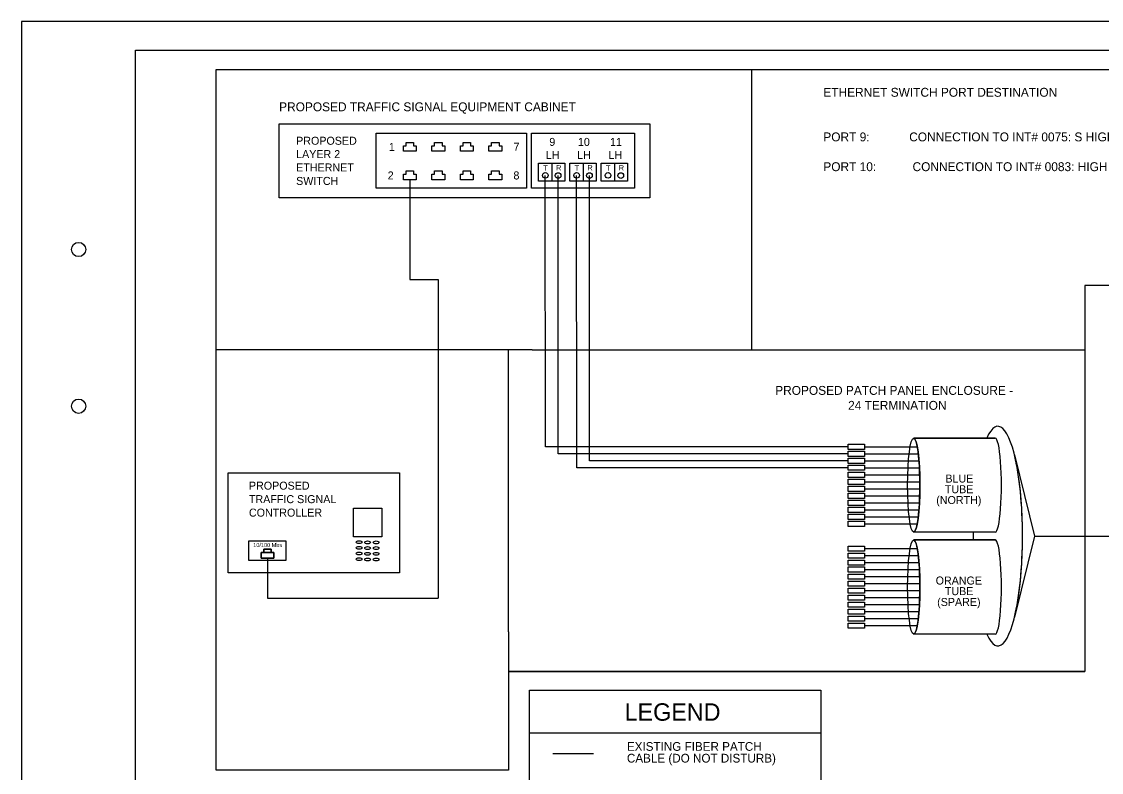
# Model space of a CAD drawing. Extents: x 1805893 to 1833564, y 708898 to 716199.
# Drawn here: x 1831322.5 to 1831701.4, y 713434.4 to 713697.9 of the extents above; entities that cross this region are included whole.
import ezdxf

# ---------------------------------------------------------------- set-up
doc = ezdxf.new("R2010")
doc.units = 0
for name, color, linetype in [('BR_P_Sub_Hidden', 7, 'Continuous'), ('SH_Border', 7, 'Continuous'), ('SH_Cut_Line', 7, 'Continuous'), ('SH_Data', 7, 'Continuous')]:
    doc.layers.add(name, color=color, linetype=linetype)

msp = doc.modelspace()

# ---------------------------------------------------------------- linework, layer by layer
at = {"layer": 'BR_P_Sub_Hidden'}
for p, q in [((1831578.6, 713681.08), (1831578.6, 713582.72)), ((1831501.65, 713582.72), (1831390.73, 713582.72)), ((1831493.37, 713483.67), (1831493.37, 713582.72)), ((1831501.65, 713582.72), (1831695.5, 713582.72)), ((1831493.37, 713483.67), (1831493.37, 713435.11)), ((1831493.37, 713469.79), (1831695.5, 713469.79))]:
    msp.add_line(p, q, dxfattribs=at)
msp.add_lwpolyline([(1831493.37, 713435.11), (1831390.73, 713435.11), (1831390.73, 713681.08), (1831814.91, 713681.08), (1831814.91, 713605.3), (1831695.5, 713605.3), (1831695.5, 713469.79), (1831493.37, 713469.79)], close=True, dxfattribs=at)
at = {"layer": 'SH_Border'}
msp.add_lwpolyline([(1831362.49, 713687.91), (1831992.49, 713687.91), (1831992.49, 713267.91), (1831362.49, 713267.91)], close=True, dxfattribs=at)
for centre in [(1831342.49, 713617.91), (1831342.49, 713562.91)]:
    msp.add_circle(centre, 2.5, dxfattribs=at)
at = {"layer": 'SH_Cut_Line'}
msp.add_lwpolyline([(1831322.49, 713257.91), (1832002.49, 713257.91), (1832002.49, 713697.91), (1831322.49, 713697.91)], close=True, dxfattribs=at)
at = {"layer": 'SH_Data'}
for p, q in [((1831508.49, 713648.17), (1831508.49, 713641.9)), ((1831519.49, 713648.17), (1831519.49, 713641.9)), ((1831530.49, 713648.17), (1831530.49, 713641.9)), ((1831506.28, 713548.67), (1831506.25, 713643.93)), ((1831510.79, 713546.21), (1831510.74, 713643.86)), ((1831517.28, 713541.3), (1831517.25, 713643.93)), ((1831521.79, 713543.75), (1831521.74, 713643.86)), ((1831458.71, 713642.38), (1831458.71, 713607.38)), ((1831458.71, 713607.38), (1831468.63, 713607.38)), ((1831468.63, 713607.38), (1831468.63, 713495.52)), ((1831612.48, 713548.67), (1831506.28, 713548.67)), ((1831618.22, 713548.67), (1831636.75, 713548.67)), ((1831664.14, 713551.7), (1831635.51, 713551.7)), ((1831635.51, 713551.7), (1831661.12, 713551.7)), ((1831635.51, 713551.7), (1831664.14, 713551.7)), ((1831612.48, 713546.21), (1831510.79, 713546.21)), ((1831618.22, 713546.21), (1831637.11, 713546.21)), ((1831670.87, 713545.81), (1831677.88, 713517.31)), ((1831612.48, 713541.3), (1831517.28, 713541.3)), ((1831612.48, 713543.75), (1831521.79, 713543.75)), ((1831618.22, 713543.75), (1831637.34, 713543.75)), ((1831618.22, 713541.3), (1831637.5, 713541.3)), ((1831618.22, 713538.84), (1831637.6, 713538.84)), ((1831618.22, 713536.38), (1831637.6, 713536.38)), ((1831618.22, 713533.93), (1831637.65, 713533.93)), ((1831618.22, 713531.47), (1831637.6, 713531.47)), ((1831618.22, 713529.01), (1831637.5, 713529.01)), ((1831618.22, 713526.56), (1831637.34, 713526.56)), ((1831618.22, 713524.1), (1831637.1, 713524.1)), ((1831618.22, 713521.64), (1831636.74, 713521.64)), ((1831664.14, 713518.66), (1831635.5, 713518.66)), ((1831664.14, 713518.66), (1831635.5, 713518.66)), ((1831664.14, 713515.96), (1831635.51, 713515.96)), ((1831635.51, 713515.96), (1831664.14, 713515.96)), ((1831677.88, 713517.31), (1831670.86, 713488.83)), ((1831677.88, 713517.31), (1831707.24, 713517.31)), ((1831618.22, 713512.93), (1831636.75, 713512.93)), ((1831618.22, 713510.47), (1831637.11, 713510.47)), ((1831408.76, 713509.53), (1831408.76, 713495.52)), ((1831618.22, 713508.01), (1831637.34, 713508.01)), ((1831618.22, 713505.56), (1831637.5, 713505.56)), ((1831618.22, 713503.1), (1831637.6, 713503.1)), ((1831618.22, 713500.64), (1831637.6, 713500.64)), ((1831408.76, 713495.52), (1831468.63, 713495.52)), ((1831618.22, 713498.19), (1831637.65, 713498.19)), ((1831618.22, 713495.73), (1831637.6, 713495.73)), ((1831618.22, 713493.27), (1831637.5, 713493.27)), ((1831618.22, 713490.82), (1831637.34, 713490.82)), ((1831618.22, 713488.36), (1831637.1, 713488.36)), ((1831618.22, 713485.9), (1831636.74, 713485.9)), ((1831664.14, 713482.92), (1831635.5, 713482.92)), ((1831664.14, 713482.92), (1831635.5, 713482.92)), ((1831508.86, 713441.01), (1831523.2, 713441.01))]:
    msp.add_line(p, q, dxfattribs=at)
for points in [[(1831412.87, 713662.07), (1831542.87, 713662.07), (1831542.87, 713636.07), (1831412.87, 713636.07)], [(1831446.88, 713658.71), (1831499.69, 713658.71), (1831499.69, 713639.44), (1831446.88, 713639.44)], [(1831501.4, 713658.71), (1831537.53, 713658.71), (1831537.53, 713639.44), (1831501.4, 713639.44)], [(1831503.85, 713648.17), (1831513.12, 713648.17), (1831513.12, 713641.9), (1831503.85, 713641.9)], [(1831514.85, 713648.17), (1831524.12, 713648.17), (1831524.12, 713641.9), (1831514.85, 713641.9)], [(1831525.85, 713648.17), (1831535.12, 713648.17), (1831535.12, 713641.9), (1831525.85, 713641.9)], [(1831612.49, 713549.57), (1831618.22, 713549.57), (1831618.22, 713547.77), (1831612.49, 713547.77)], [(1831612.48, 713544.65), (1831618.21, 713544.65), (1831618.21, 713542.85), (1831612.48, 713542.85)], [(1831612.49, 713547.11), (1831618.22, 713547.11), (1831618.22, 713545.31), (1831612.49, 713545.31)], [(1831612.48, 713542.26), (1831618.21, 713542.26), (1831618.21, 713540.46), (1831612.48, 713540.46)], [(1831395.03, 713539.47), (1831455.03, 713539.47), (1831455.03, 713504.47), (1831395.03, 713504.47)], [(1831612.48, 713539.74), (1831618.21, 713539.74), (1831618.21, 713537.94), (1831612.48, 713537.94)], [(1831612.48, 713537.28), (1831618.21, 713537.28), (1831618.21, 713535.48), (1831612.48, 713535.48)], [(1831612.48, 713534.83), (1831618.21, 713534.83), (1831618.21, 713533.03), (1831612.48, 713533.03)], [(1831612.48, 713532.37), (1831618.21, 713532.37), (1831618.21, 713530.57), (1831612.48, 713530.57)], [(1831612.48, 713529.91), (1831618.21, 713529.91), (1831618.21, 713528.11), (1831612.48, 713528.11)], [(1831438.89, 713527.12), (1831448.89, 713527.12), (1831448.89, 713517.12), (1831438.89, 713517.12)], [(1831612.48, 713527.46), (1831618.21, 713527.46), (1831618.21, 713525.66), (1831612.48, 713525.66)], [(1831612.48, 713525), (1831618.21, 713525), (1831618.21, 713523.2), (1831612.48, 713523.2)], [(1831612.48, 713522.54), (1831618.21, 713522.54), (1831618.21, 713520.74), (1831612.48, 713520.74)], [(1831402.26, 713515.71), (1831415.26, 713515.71), (1831415.26, 713508.71), (1831402.26, 713508.71)], [(1831406.54, 713511.51), (1831410.99, 713511.51), (1831410.99, 713509.53), (1831406.54, 713509.53)], [(1831407.46, 713512.68), (1831410.06, 713512.68), (1831410.06, 713511.51), (1831407.46, 713511.51)], [(1831612.49, 713513.83), (1831618.22, 713513.83), (1831618.22, 713512.03), (1831612.49, 713512.03)], [(1831612.49, 713511.37), (1831618.22, 713511.37), (1831618.22, 713509.57), (1831612.49, 713509.57)], [(1831612.48, 713508.91), (1831618.21, 713508.91), (1831618.21, 713507.11), (1831612.48, 713507.11)], [(1831612.48, 713506.52), (1831618.21, 713506.52), (1831618.21, 713504.72), (1831612.48, 713504.72)], [(1831612.48, 713504), (1831618.21, 713504), (1831618.21, 713502.2), (1831612.48, 713502.2)], [(1831612.48, 713501.54), (1831618.21, 713501.54), (1831618.21, 713499.74), (1831612.48, 713499.74)], [(1831612.48, 713499.09), (1831618.21, 713499.09), (1831618.21, 713497.29), (1831612.48, 713497.29)], [(1831612.48, 713496.63), (1831618.21, 713496.63), (1831618.21, 713494.83), (1831612.48, 713494.83)], [(1831612.48, 713494.17), (1831618.21, 713494.17), (1831618.21, 713492.37), (1831612.48, 713492.37)], [(1831612.48, 713491.72), (1831618.21, 713491.72), (1831618.21, 713489.92), (1831612.48, 713489.92)], [(1831612.48, 713489.26), (1831618.21, 713489.26), (1831618.21, 713487.46), (1831612.48, 713487.46)], [(1831612.48, 713486.8), (1831618.21, 713486.8), (1831618.21, 713485), (1831612.48, 713485)], [(1831500.7, 713463.24), (1831602.93, 713463.24), (1831602.93, 713448.13), (1831500.7, 713448.13)], [(1831602.93, 713463.24), (1831602.93, 713273.07), (1831500.7, 713273.07), (1831500.7, 713463.24)]]:
    msp.add_lwpolyline(points, close=True, dxfattribs=at)
for points in [[(1831460.01, 713654.36), (1831460.94, 713654.36), (1831460.94, 713652.38), (1831456.49, 713652.38), (1831456.49, 713654.36), (1831457.41, 713654.36)], [(1831457.41, 713654.36), (1831457.41, 713655.53), (1831460.01, 713655.53), (1831460.01, 713654.36)], [(1831470.01, 713654.36), (1831470.94, 713654.36), (1831470.94, 713652.38), (1831466.49, 713652.38), (1831466.49, 713654.36), (1831467.41, 713654.36)], [(1831467.41, 713654.36), (1831467.41, 713655.53), (1831470.01, 713655.53), (1831470.01, 713654.36)], [(1831480.01, 713654.36), (1831480.94, 713654.36), (1831480.94, 713652.38), (1831476.49, 713652.38), (1831476.49, 713654.36), (1831477.41, 713654.36)], [(1831477.41, 713654.36), (1831477.41, 713655.53), (1831480.01, 713655.53), (1831480.01, 713654.36)], [(1831490.01, 713654.36), (1831490.94, 713654.36), (1831490.94, 713652.38), (1831486.49, 713652.38), (1831486.49, 713654.36), (1831487.41, 713654.36)], [(1831487.41, 713654.36), (1831487.41, 713655.53), (1831490.01, 713655.53), (1831490.01, 713654.36)], [(1831460.01, 713644.36), (1831460.94, 713644.36), (1831460.94, 713642.38), (1831456.49, 713642.38), (1831456.49, 713644.36), (1831457.41, 713644.36)], [(1831457.41, 713644.36), (1831457.41, 713645.53), (1831460.01, 713645.53), (1831460.01, 713644.36)], [(1831470.01, 713644.36), (1831470.94, 713644.36), (1831470.94, 713642.38), (1831466.49, 713642.38), (1831466.49, 713644.36), (1831467.41, 713644.36)], [(1831467.41, 713644.36), (1831467.41, 713645.53), (1831470.01, 713645.53), (1831470.01, 713644.36)], [(1831480.01, 713644.36), (1831480.94, 713644.36), (1831480.94, 713642.38), (1831476.49, 713642.38), (1831476.49, 713644.36), (1831477.41, 713644.36)], [(1831477.41, 713644.36), (1831477.41, 713645.53), (1831480.01, 713645.53), (1831480.01, 713644.36)], [(1831490.01, 713644.36), (1831490.94, 713644.36), (1831490.94, 713642.38), (1831486.49, 713642.38), (1831486.49, 713644.36), (1831487.41, 713644.36)], [(1831487.41, 713644.36), (1831487.41, 713645.53), (1831490.01, 713645.53), (1831490.01, 713644.36)], [(1831410.06, 713511.51), (1831407.46, 713511.51), (1831406.54, 713511.51), (1831406.54, 713509.53), (1831410.99, 713509.53), (1831410.99, 713511.51), (1831410.06, 713511.51)], [(1831407.46, 713511.51), (1831410.06, 713511.51), (1831410.06, 713512.68), (1831407.46, 713512.68), (1831407.46, 713511.51)]]:
    msp.add_lwpolyline(points, dxfattribs=at)
for centre in [(1831506.25, 713643.93), (1831506.25, 713643.93), (1831510.74, 713643.86), (1831517.25, 713643.93), (1831517.25, 713643.93), (1831521.74, 713643.86), (1831528.25, 713643.93), (1831528.25, 713643.93), (1831532.74, 713643.86)]:
    msp.add_circle(centre, 0.99, dxfattribs=at)
for centre, major_axis, ratio, start_param, end_param in [((1831665.04, 713517.33), (0, -38.55), 0.22436, 5.816039, 9.895092), ((1831635.51, 713535.18), (0, -16.52), 0.129904, 0, 3.141593), ((1831664.14, 713535.18), (0, -16.52), 0.129904, 0, 3.141593), ((1831664.14, 713535.18), (0, -16.52), 0.129904, 0, 3.141593), ((1831665.04, 713517.33), (0, -38.55), 0.22436, 0.738594, 2.402034), ((1831665.04, 713517.33), (0, -38.55), 0.22436, 4.678099, 4.748111), ((1831665.04, 713517.33), (0, -38.55), 0.22436, 4.678099, 4.748111), ((1831635.51, 713499.44), (0, -16.52), 0.129904, 0, 3.141593), ((1831664.14, 713499.44), (0, -16.52), 0.129904, 0, 3.141593), ((1831664.14, 713499.44), (0, -16.52), 0.129904, 0, 3.141593)]:
    msp.add_ellipse(centre, major_axis=major_axis, ratio=ratio, start_param=start_param, end_param=end_param, dxfattribs=at)
for centre, major_axis, ratio in [((1831635.51, 713535.18), (0, -16.52), 0.129904), ((1831440.9, 713515.21), (1, 0), 0.5), ((1831443.89, 713515.12), (1, 0), 0.5), ((1831446.89, 713515.12), (1, 0), 0.5), ((1831635.51, 713499.44), (0, -16.52), 0.129904), ((1831440.9, 713513.21), (1, 0), 0.5), ((1831440.9, 713511.21), (1, 0), 0.5), ((1831443.89, 713513.12), (1, 0), 0.5), ((1831443.89, 713511.12), (1, 0), 0.5), ((1831446.89, 713513.12), (1, 0), 0.5), ((1831446.89, 713511.12), (1, 0), 0.5), ((1831440.9, 713509.21), (1, 0), 0.5), ((1831443.89, 713509.12), (1, 0), 0.5), ((1831446.89, 713509.12), (1, 0), 0.5)]:
    msp.add_ellipse(centre, major_axis=major_axis, ratio=ratio, dxfattribs=at)

# ---------------------------------------------------------------- texts
for s, height, p in [('ETHERNET SWITCH PORT DESTINATION', 3.1201, (1831603.8, 713671.53)), ('PROPOSED TRAFFIC SIGNAL EQUIPMENT CABINET', 3.1201, (1831412.87, 713666.44)), ('PORT 9:            CONNECTION TO INT# 0075: S HIGH ST AT MAIN ST', 3.1201, (1831603.8, 713655.87)), ('PROPOSED ', 2.808, (1831418.82, 713654.68)), ('1', 2.81, (1831451.35, 713652.5)), ('7', 2.81, (1831495.09, 713652.55)), ('9', 2.81, (1831507.65, 713654.27)), ('10', 2.808, (1831517.7, 713654.27)), ('11', 2.808, (1831528.96, 713654.27)), ('LAYER 2 ', 2.808, (1831418.82, 713649.99)), ('LH', 2.808, (1831506.42, 713649.7)), ('LH', 2.808, (1831517.42, 713649.7)), ('LH', 2.808, (1831528.42, 713649.7)), ('ETHERNET ', 2.808, (1831418.82, 713645.31)), ('T', 1.87, (1831505.54, 713645.59)), ('R', 1.87, (1831510.03, 713645.65)), ('T', 1.87, (1831516.54, 713645.59)), ('R', 1.87, (1831521.03, 713645.65)), ('T', 1.87, (1831527.54, 713645.59)), ('R', 1.87, (1831532.03, 713645.65)), ('PORT 10:           CONNECTION TO INT# 0083: HIGH ST AT MOUND ST', 3.1201, (1831603.8, 713645.42)), ('SWITCH', 2.808, (1831418.82, 713640.58)), ('2', 2.81, (1831450.93, 713642.5)), ('8', 2.81, (1831495.07, 713642.5)), ('PROPOSED PATCH PANEL ENCLOSURE - ', 3.1201, (1831586.92, 713566.9)), ('24 TERMINATION', 3.1201, (1831612.49, 713561.65)), ('BLUE', 2.808, (1831646.63, 713536.11)), ('PROPOSED', 2.808, (1831402.26, 713533.62)), ('TUBE', 2.808, (1831646.43, 713532.37)), ('TRAFFIC SIGNAL ', 2.8081, (1831402.26, 713528.89)), ('(NORTH)', 2.808, (1831643.42, 713528.58)), ('CONTROLLER', 2.808, (1831402.26, 713524.16)), ('10/100 Mbs', 1.404, (1831403.78, 713513.48)), ('ORANGE', 2.808, (1831643.21, 713500.32)), ('TUBE', 2.808, (1831646.43, 713496.59)), ('(SPARE)', 2.808, (1831643.74, 713492.8)), ('LEGEND', 6.119, (1831534.07, 713452.52)), ('EXISTING FIBER PATCH ', 3.0596, (1831534.88, 713441.96)), ('CABLE (DO NOT DISTURB)', 3.0596, (1831534.88, 713437.84))]:
    msp.add_text(s, height=height, dxfattribs=at).set_placement(p)

doc.saveas('drawing.dxf')
